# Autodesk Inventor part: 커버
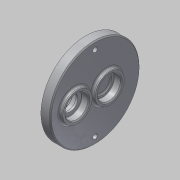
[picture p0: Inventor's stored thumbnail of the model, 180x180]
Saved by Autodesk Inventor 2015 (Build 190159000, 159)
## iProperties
Created: 2016-02
Part Number: 커버
Material: 알루미늄 6061
Document SubType Name: Modeling
Designer: mduedu
Density: 2.71 g/cm^3
Appearance: Aluminum - Flat
Author: mduedu
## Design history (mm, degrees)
sketch "스케치1"
  geometry: C1 r 43 at (0, 0); 1 further point
  constraints: 1 centre point, 1 coincident
  dimensions: "d0" = 86 diameter of C1
extrude "돌출1" new body sketch "스케치1" distance "d1" = 9; taper "d2" = 0 deg
sketch "스케치2"
  geometry: C1 r 14 at (0, 11); 1 further point
  constraints: 1 centre point, 1 vertical alignment
  dimensions: "d3" = 28 diameter of C1; "d6" = 11 distance of C1.centre point (0, 0)
extrude "돌출2" join sketch "스케치2" distance "d7" = 3; taper "d8" = 0 deg
sketch "스케치3"
  geometry: C1 r 14 at (0, -20); 1 further point
  constraints: 1 centre point, 1 vertical alignment
  dimensions: "d9" = 28 diameter of C1; "d10" = 20 distance of C1.centre point (0, 0)
extrude "돌출3" join sketch "스케치3" distance "d11" = 3; taper "d12" = 0 deg
hole "구멍1" diameter "d15" = 22; stored, may be unused: countersink angle "d19" = 90 deg, drill point angle "d21" = 0 deg; dims "d13" = 10, "d14" = 10, "d16" = 6, "d17" = 4, "d18" = 2, "d20" = 7
hole "구멍2" diameter "d24" = 18; stored, may be unused: countersink angle "d28" = 90 deg, drill point angle "d30" = 0 deg; dims "d22" = 10, "d23" = 10, "d25" = 6, "d26" = 4, "d27" = 2, "d29" = 1
hole "구멍3" diameter "d33" = 22; stored, may be unused: countersink angle "d37" = 90 deg, drill point angle "d39" = 0 deg; dims "d34" = 6, "d35" = 4, "d36" = 2, "d38" = 7, "d73" = 10, "d74" = 10
sketch "스케치4"
  geometry: C1 r 14 at (0, -20) reference; C2 r 18 at (0, -20); 1 further point
  constraints: 1 centre point, 1 coincident
  dimensions: "d40" = 36 diameter of C2
extrude "돌출4" join sketch "스케치4" distance "d41" = 4; taper "d42" = 0 deg
hole "구멍4" diameter "d45" = 22; stored, may be unused: countersink angle "d49" = 90 deg, drill point angle "d51" = 0 deg; dims "d43" = 10, "d44" = 10, "d46" = 6, "d47" = 4, "d48" = 2, "d50" = 7
hole "구멍5" diameter "d54" = 15; stored, may be unused: countersink angle "d58" = 90 deg, drill point angle "d60" = 0 deg; dims "d52" = 10, "d53" = 10, "d55" = 6, "d56" = 4, "d57" = 2, "d59" = 7
fillet "모깎기1" dims "d61" = 0.3
fillet "모깎기2" dims "d62" = 2
chamfer "모따기1" distance "d63" = 1; stored, may be unused: second distance "d64" = 2, angle "d65" = 45 deg
fillet "모깎기6" dims "d88" = 2
sketch "스케치5" dims "d67" = 72
  geometry: 4 further points
  constraints: 2 horizontal alignment, 1 coincident, 5 other
  dimensions: "d71" = 360 deg dimension on point (0, 0) point (-36, 0) (derived)
fillet "모깎기4" dims "d75" = 2
sketch "스케치6"
  geometry: 2 further points
hole "구멍6" sketch "스케치6" at (36, 0), (-36, 0) diameter "d76" = 4.5; stored, may be unused: countersink angle "d80" = 90 deg, drill point angle "d82" = 0 deg; dims "d77" = 6, "d78" = 8, "d79" = 4.6, "d81" = 8
chamfer "모따기2" distance "d90" = 1; stored, may be unused: second distance "d91" = 2, angle "d92" = 45 deg
node "솔리드1"
